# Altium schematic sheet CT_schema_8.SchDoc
size 391 x 238 mm
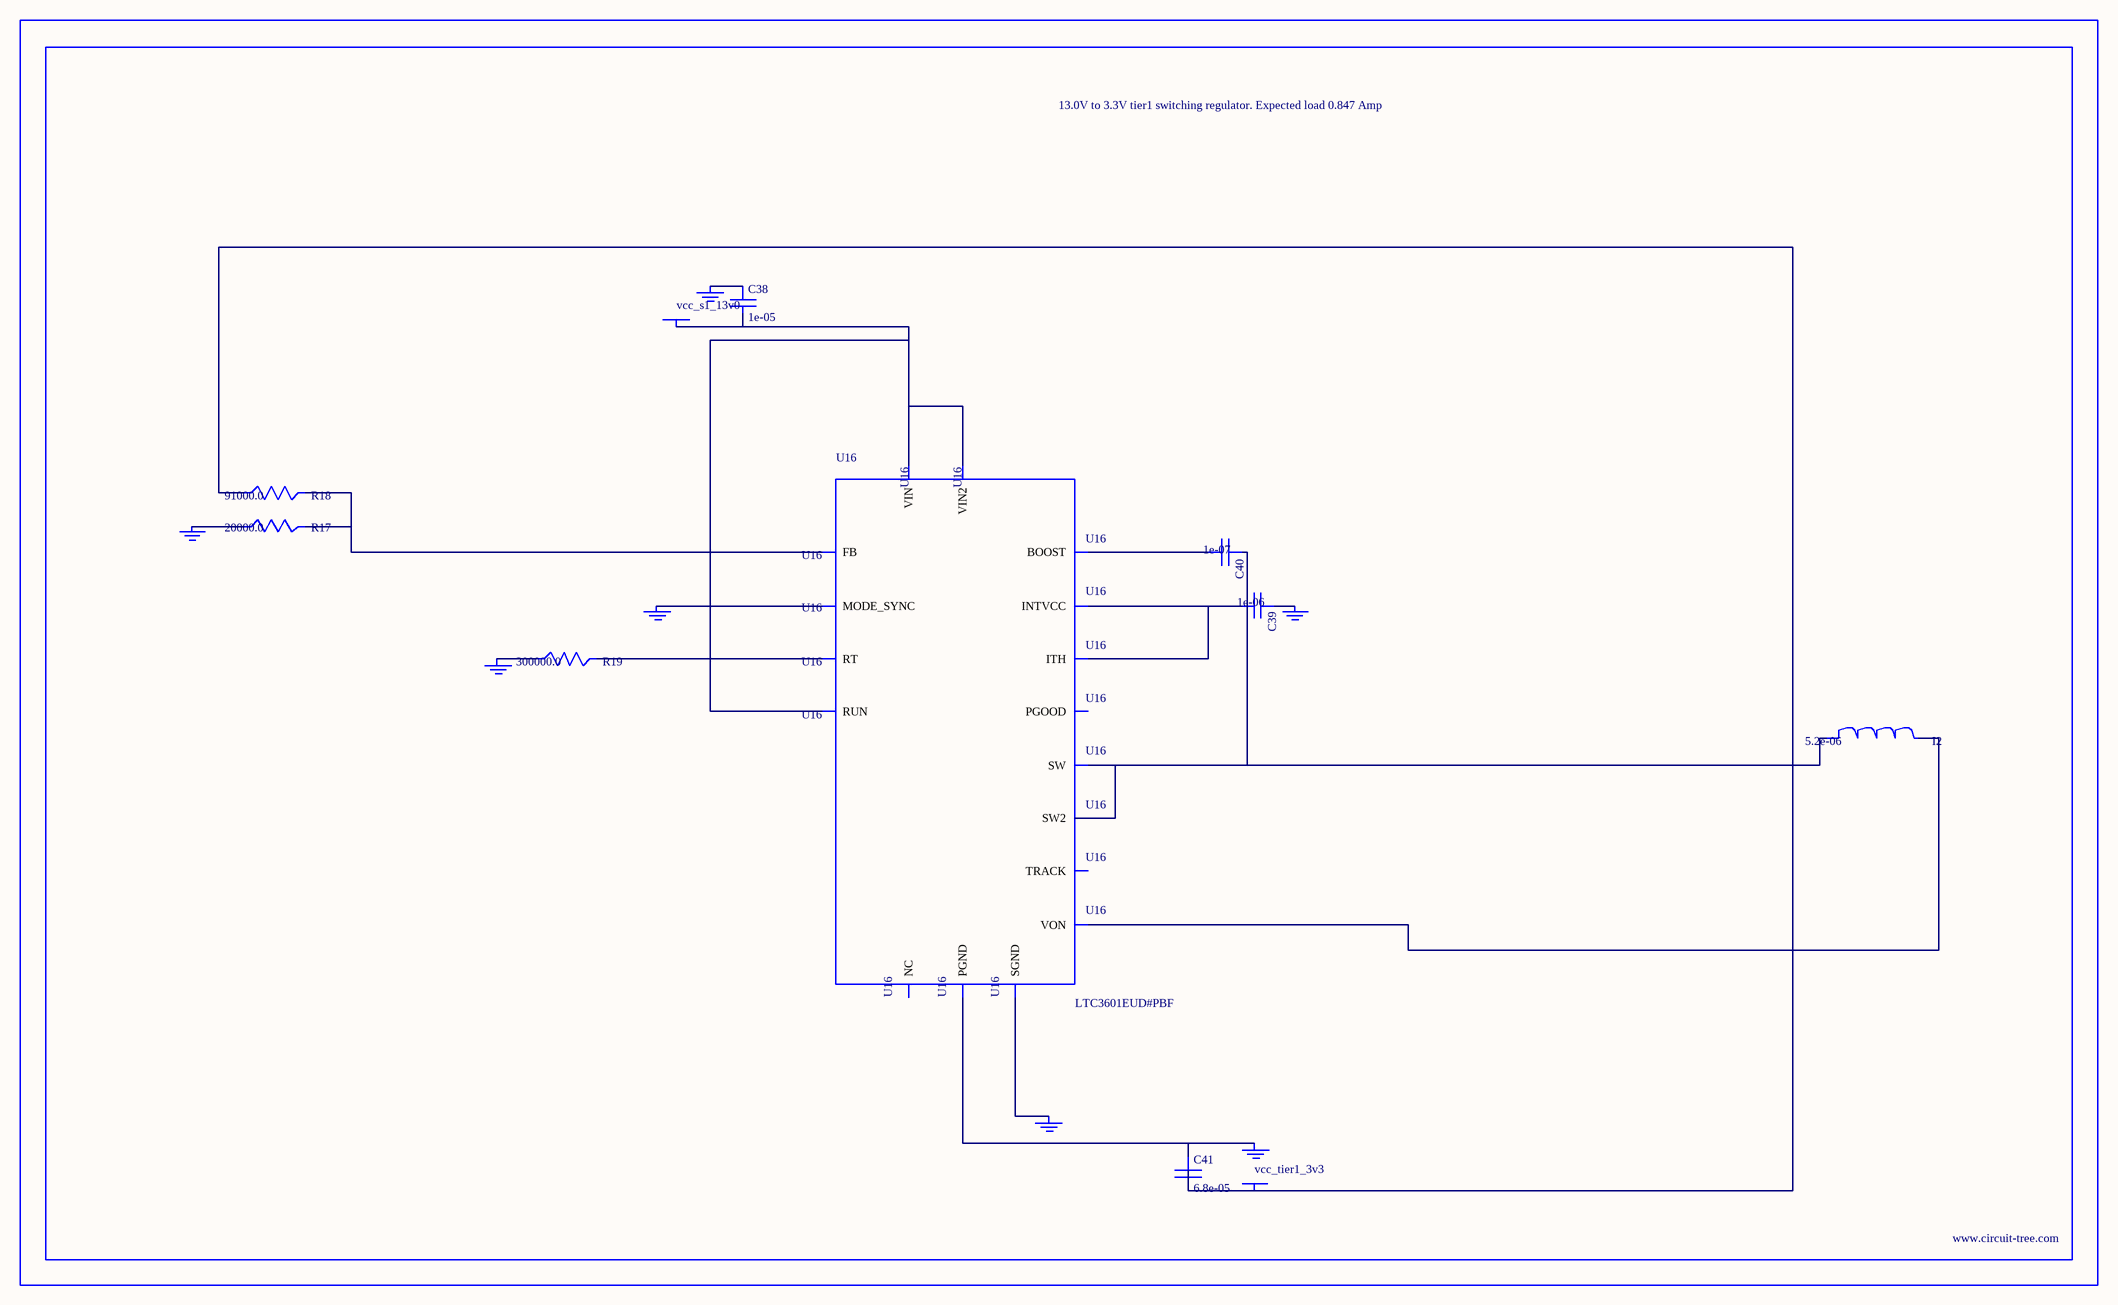
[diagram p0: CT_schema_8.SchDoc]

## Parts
BORDER7  (no value)
C38  1e-05  [C0805]
C39  1e-06  [C0603]
C40  1e-07  [C0402]
C41  6.8e-05  [2220]
GND_INSTANCE_7_0  (no value)
GND_INSTANCE_7_1  (no value)
GND_INSTANCE_7_2  (no value)
GND_INSTANCE_7_3  (no value)
GND_INSTANCE_7_4  (no value)
GND_INSTANCE_7_5  (no value)
GND_INSTANCE_7_6  (no value)
I2  5.2e-06  [DR1040]
POWER_INSTANCE_7_0  vcc_s1_13v0
POWER_INSTANCE_7_1  vcc_tier1_3v3
R17  20000.0  [R0603]
R18  91000.0  [R0603]
R19  300000.0  [R0603]
U16  LTC3601EUD#PBF  [QFN-16_EP]

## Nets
NetC38_1: C38.1 GND_INSTANCE_7_5.0(GND)
NetC38_2: C38.2 POWER_INSTANCE_7_0.0(PWR) U16.14(RUN) U16.15(VIN) U16.16(VIN2)
NetC39_1: C39.1 GND_INSTANCE_7_1.0(GND)
NetC39_2: C39.2 U16.7(INTVCC) U16.12(ITH)
NetC40_1: C40.1 I2.1 U16.3(SW) U16.4(SW2)
NetC40_2: C40.2 U16.6(BOOST)
NetC41_1: C41.1 GND_INSTANCE_7_6.0(GND) U16.17(PGND)
NetC41_2: C41.2 I2.2 POWER_INSTANCE_7_1.0(PWR) R18.1 U16.8(VON)
NetGND_INSTANCE_7_0_0: GND_INSTANCE_7_0.0(GND) U16.1(MODE_SYNC)
NetGND_INSTANCE_7_2_0: GND_INSTANCE_7_2.0(GND) U16.9(SGND)
NetGND_INSTANCE_7_3_0: GND_INSTANCE_7_3.0(GND) R19.1
NetGND_INSTANCE_7_4_0: GND_INSTANCE_7_4.0(GND) R17.1
NetR17_2: R17.2 R18.2 U16.11(FB)
NetR19_2: R19.2 U16.10(RT)

Not connected (* = marked no-connect by the designer): U16 2(PGOOD) 5(NC) 13(TRACK)

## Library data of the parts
BORDER7 = BORDER_PAGE7
C38 = C0805C106K8RACTU
C39 = C0603C105K3RACTU
C40 = C0402C104K3RACTU
C41 = C5750X5R1A686M
GND_INSTANCE_7_0-GND_INSTANCE_7_6 = GND
I2 = DR1040-5R2-R
POWER_INSTANCE_7_0 POWER_INSTANCE_7_1 = PWR
R17 = RC0603JR-0720KL
R18 = RC0603JR-0791KL
R19 = RC0603JR-07300KL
